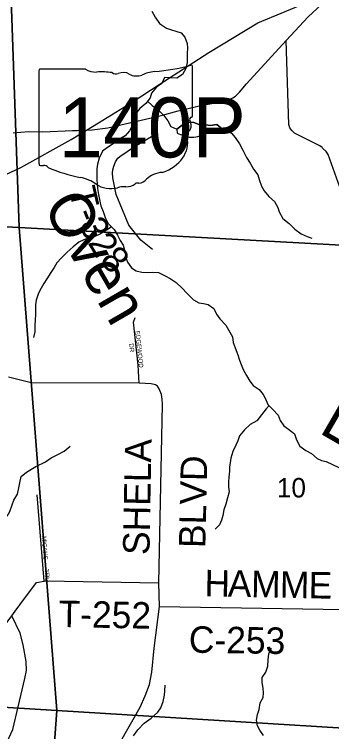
# Model space of a CAD drawing. Extents: x 1624196 to 2029251, y 146837 to 440034.
# Drawn here: x 1866396 to 1869991, y 270363 to 278490 of the extents above; entities that cross this region are included whole.
import ezdxf

# ---------------------------------------------------------------- set-up
doc = ezdxf.new("R2010")
doc.units = 0
for name, color, linetype in [('GM_P_State_Alignment', 7, 'Continuous'), ('GM_P_State_Location', 7, 'Continuous'), ('GM_P_State_Shield', 7, 'Continuous'), ('GM_X_County_Road', 7, 'Continuous'), ('GM_X_County_Road_Text', 7, 'Continuous'), ('GM_X_Minor_Lake', 7, 'Continuous'), ('GM_X_Minor_River', 7, 'Continuous'), ('GM_X_Minor_River_Text', 7, 'Continuous'), ('GM_X_Section', 7, 'Continuous'), ('GM_X_Section_Text', 7, 'Continuous'), ('GM_X_State_Route', 7, 'Continuous'), ('GM_X_Township_Road', 7, 'Continuous'), ('GM_X_Township_Road_Text', 7, 'Continuous'), ('GM_X_Township_Subdivision', 7, 'Continuous'), ('GM_X_Township_Subdivision_Text', 7, 'Continuous')]:
    doc.layers.add(name, color=color, linetype=linetype)

msp = doc.modelspace()

# ---------------------------------------------------------------- linework, layer by layer
at = {"layer": 'GM_P_State_Alignment'}
for points in [[(1867348.5, 277261), (1867740.4, 277501.5), (1868036.8, 277693.6), (1868599.3, 278058.2), (1869156.1, 278392.2), (1869792.3, 278662.6), (1870063.5, 278785.3), (1870460.4, 278964.8), (1871144.4, 279012.5), (1871212, 279012.5), (1872003.4, 279012.5), (1872655.6, 278996.6), (1872814.3, 279012), (1873399, 279068.6)], [(1867214.4, 277178.7), (1867348.5, 277261)], [(1861874.5, 274742.2), (1862064.2, 274850.8), (1862146.9, 274886.5), (1862221.6, 274909.2), (1862468.2, 274980.7), (1862817.1, 275066.7), (1863068.6, 275126.7), (1863088.2, 275172.1), (1863130.1, 275268.7), (1863334.2, 275354.2), (1863587.6, 275464), (1863663, 275496.7), (1863811.4, 275560.9), (1863954.5, 275640.5), (1864133.3, 275718.1), (1864797.6, 276006.3), (1865481.6, 276292.6), (1866467.8, 276753.9), (1867040.5, 277072), (1867214.4, 277178.7)]]:
    msp.add_lwpolyline(points, dxfattribs=at)
at = {"layer": 'GM_P_State_Shield'}
for p, q in [((1866675.2, 277851.2), (1866675.2, 276794.6)), ((1867202, 277869.4), (1866692.4, 277869.4)), ((1868415.4, 277342.9), (1868415.4, 277895.6)), ((1868415.3, 277343), (1868415.4, 277342.9))]:
    msp.add_line(p, q, dxfattribs=at)
for centre, major_axis, start_param, end_param in [((1866695.2, 277853.5), (20.2, 0), 1.712693, 3.28349), ((1867323.4, 277992.1), (195.5, 0), 4.042523, 4.731795), ((1867795.5, 279310), (1845.5, 0), 4.814394, 5.042369), ((1868396.1, 277897.9), (19.4, 0), 6.141152, 7.989035), ((1867388.2, 277276.2), (702, 0), 1.404758, 1.657858), ((1867547.6, 277859), (56.4, 0), 3.836095, 5.185415), ((1867630.4, 277736.8), (117.3, 0), 0.950623, 2.079405), ((1867781.8, 277904.3), (141.1, 0), 4.081561, 5.145723), ((1868030.9, 277546.7), (371.3, 0), 1.699011, 2.107814), ((1868411, 277302.3), (30, 0), 1.883978, 3.671073), ((1868220.2, 277232.4), (180, 0), 5.934695, 6.695948), ((1868394.8, 277340.7), (20.7, 0), 5.05454, 6.418171), ((1868484.8, 277111.5), (130.9, 0), 2.387724, 3.262537), ((1867898.9, 277041.2), (461.6, 0), 5.101752, 6.440018), ((1866695.4, 276792.3), (20.3, 0), 3.00124, 4.508301), ((1866698.4, 276900.4), (155.2, 0), 4.665946, 4.897461), ((1866730.2, 276733.6), (56, 0), 0.519207, 1.627899), ((1867436.8, 277683), (1332.7, 0), 4.195997, 4.488961), ((1867039.5, 276319.9), (417, 0), 0.823519, 1.323587), ((1868093.6, 276497.9), (252.8, 0), 1.647645, 2.488434), ((1867490.4, 276728.4), (264.6, 0), 4.026481, 4.996735), ((1867662.7, 276649.3), (141, 0), 4.691044, 5.507374), ((1867790.2, 276546.9), (39.7, 0), 1.147584, 2.315152), ((1867773.3, 276692.2), (149.1, 0), 4.937069, 5.64225), ((1867643.3, 276363.1), (217.4, 0), 1.495662, 1.94098)]:
    msp.add_ellipse(centre, major_axis=major_axis, ratio=0.8, start_param=start_param, end_param=end_param, dxfattribs=at)
at = {"layer": 'GM_X_County_Road'}
for points in [[(1868041.8, 271781.7), (1868033.7, 272048.3), (1868074.8, 274068), (1868071.3, 274130.9), (1868064.3, 274182.5), (1868037, 274247.1), (1868016.1, 274277.8), (1867995.5, 274293.7), (1867946.8, 274302.3), (1867809, 274312.2), (1866587.5, 274314.3), (1866329.7, 274381.2)], [(1866646.8, 267515.1), (1866874.7, 267543), (1867025.1, 267561.1), (1867079.3, 267579.1), (1867148.5, 267621.3), (1867205.7, 267684.5), (1867254.5, 267863.2), (1867359.7, 268076.7), (1867416.6, 268218.5), (1867445.5, 268362.4), (1867458.4, 268492.5), (1867424.5, 268793.1), (1867389.6, 269254), (1867374.8, 269424.3), (1867356.1, 269620.7), (1867409.5, 269828.6), (1867508.7, 270046.1), (1867585.8, 270227.8), (1867820.2, 270640.6), (1867879, 270770.3), (1867927.8, 270896.1), (1867954.6, 271036.1), (1867980.5, 271310.3), (1868041.8, 271781.7)], [(1868041.8, 271781.7), (1870358.7, 271742.5)]]:
    msp.add_lwpolyline(points, dxfattribs=at)
at = {"layer": 'GM_X_Minor_Lake'}
for points in [[(1868752.3, 277189.1), (1868688.5, 277241.6), (1868614.3, 277231.9), (1868564.3, 277238.1), (1868498.2, 277238.4), (1868428.2, 277264.8), (1868366.1, 277267.1), (1868297.8, 277235.4), (1868235.5, 277187.5)], [(1868235.5, 277187.5), (1868239.3, 277145.4), (1868279.3, 277129.2), (1868327.4, 277116.9), (1868375.3, 277098.7), (1868427.4, 277098.4), (1868475.5, 277106.2), (1868519.7, 277122), (1868565.8, 277143.9), (1868615.9, 277149.7), (1868662, 277151.5), (1868706.2, 277175.3), (1868752.3, 277189.1)]]:
    msp.add_lwpolyline(points, dxfattribs=at)
at = {"layer": 'GM_X_Minor_River'}
for points in [[(1867953, 278524.2), (1867990.8, 278457.9), (1868038.5, 278387.5), (1868118.4, 278335), (1868174.4, 278314.6), (1868224.4, 278298.4), (1868286.4, 278282), (1868326.3, 278231.7), (1868352, 278161.4), (1868355.8, 278107.3), (1868355.5, 278047.1), (1868355.3, 277997), (1868353, 277942.9), (1868338.7, 277874.8), (1868302.4, 277808.8), (1868236.1, 277765), (1868164, 277771.3), (1868097.9, 277775.6), (1868065.6, 277707.6), (1868007.3, 277663.8), (1867950.9, 277595.9), (1867934.7, 277545.8), (1867886.3, 277479.9), (1867815.9, 277424.1), (1867765.6, 277360.1), (1867749.2, 277294.1), (1867737, 277240), (1867700.6, 277170), (1867650.3, 277112.1), (1867578, 277070.3), (1867525.7, 277030.4), (1867449.4, 276980.7), (1867395.1, 276938.8), (1867356.7, 276860.8), (1867338.4, 276792.7), (1867330.2, 276740.6), (1867329.6, 276620.3), (1867333.4, 276566.2), (1867337.2, 276516), (1867348.9, 276447.8), (1867364.6, 276371.5), (1867376.4, 276319.3), (1867402.1, 276255.1), (1867425.9, 276186.8), (1867457.6, 276120.5), (1867525.4, 276052), (1867565.2, 275987.6), (1867595, 275929.3), (1867628.8, 275875), (1867646.5, 275802.8), (1867658.2, 275736.6), (1867678, 275682.3), (1867721.8, 275618), (1867777.7, 275585.6), (1867839.7, 275567.3), (1867907.9, 275567), (1867962, 275570.7), (1868030, 275566.4), (1868104, 275528), (1868159.9, 275497.6), (1868227.8, 275451.2), (1868295.6, 275386.7), (1868349.5, 275330.3), (1868425.3, 275255.8), (1868487.2, 275221.4), (1868539.2, 275213.2), (1868591.3, 275202.9), (1868655.2, 275158.5), (1868684.9, 275092.2), (1868722.8, 275039.9), (1868790.6, 274969.4), (1868836.3, 274891), (1868866.1, 274836.7), (1868875.8, 274770.5), (1868897.6, 274712.2), (1868929.3, 274631.9), (1868947, 274573.7), (1868966.8, 274523.4), (1868986.6, 274465.2), (1869024.4, 274398.9), (1869062.2, 274334.5), (1869102, 274284.2), (1869169.9, 274239.8)], [(1867905.4, 277505.9), (1867956.3, 277455.5), (1868024.2, 277407.1), (1868090, 277344.6), (1868135.8, 277282.2), (1868169.6, 277217.9), (1868235.5, 277187.5), (1868297.8, 277235.4), (1868366.1, 277267.1), (1868428.2, 277264.8), (1868498.2, 277238.4), (1868564.3, 277238.1), (1868614.3, 277231.9), (1868688.5, 277241.6), (1868752.3, 277189.1), (1868800.4, 277186.9), (1868856.3, 277144.5), (1868896.1, 277094.2), (1868945.9, 277023.8), (1868983.6, 276951.5), (1869027.3, 276867), (1869069.1, 276802.7), (1869106.9, 276736.3), (1869154.6, 276670), (1869170.4, 276619.8), (1869194.1, 276541.5), (1869225.9, 276489.2), (1869279.8, 276426.8), (1869341.6, 276370.3), (1869379.4, 276302), (1869395.2, 276251.8), (1869438.9, 276177.4), (1869510.7, 276118.9), (1869572.6, 276054.5), (1869646.4, 276004), (1869714.4, 275973.6), (1869766.4, 275955.3)], [(1867495.5, 276082.2), (1867457.3, 276054.3), (1867371, 276002.6), (1867300.7, 275970.8), (1867232.5, 275955.1), (1867182.4, 275935.3), (1867128.2, 275909.5), (1867061.8, 275855.6), (1866993.5, 275795.8), (1866929.1, 275732), (1866878.8, 275676), (1866846.5, 275622.1), (1866810.2, 275566.1), (1866763.8, 275492.1), (1866731.5, 275440.1), (1866701.2, 275386.1), (1866670.9, 275330.1), (1866642.5, 275252.1), (1866634.3, 275198), (1866636, 275141.8), (1866635.8, 275083.7), (1866631.5, 275031.6), (1866629.2, 274961.4), (1866628.9, 274893.2), (1866614.6, 274829.1)], [(1869169.9, 274239.8), (1869215.7, 274183.4), (1869239.5, 274133.2), (1869269.3, 274070.9), (1869327.1, 274008.5), (1869384.9, 273950.1), (1869406.7, 273887.8), (1869448.5, 273829.5), (1869500.4, 273791.1), (1869570.3, 273738.7), (1869594, 273670.4), (1869631.8, 273598), (1869699.6, 273547.6), (1869761.6, 273515.2), (1869825.4, 273458.8), (1869877.4, 273434.5), (1869927.4, 273424.2), (1870073.7, 273357.2)], [(1869281, 274058.2), (1869249, 274020.9), (1869194.7, 273951), (1869142.3, 273885), (1869068, 273843.3), (1869003.6, 273781.4), (1868947.2, 273713.5), (1868927, 273659.5), (1868904.7, 273607.4), (1868872.3, 273537.4), (1868850, 273461.3), (1868834.6, 273361.6)], [(1866638.3, 273369.1), (1866750.6, 273421), (1866812.9, 273466.8), (1866889.2, 273504.5), (1866959.4, 273540.3), (1867027.8, 273596.1)], [(1866316.1, 272805), (1866346.5, 272858.9), (1866371, 272932.8), (1866389.4, 272984.7), (1866429.9, 273054.4), (1866446.5, 273126.4), (1866458.9, 273182.3), (1866471.5, 273252.3), (1866531.8, 273303.9), (1866638.3, 273369.1)], [(1868834.6, 273361.6), (1868832.3, 273313.8), (1868825.8, 273245.8), (1868821.4, 273193.8), (1868820.9, 273131.7), (1868830.5, 273081.6), (1868811.9, 273011.7), (1868791.4, 272939.8), (1868770.9, 272875.8), (1868756.4, 272813.9), (1868744, 272757.9), (1868719.6, 272706), (1868669.2, 272658.4)], [(1869218.4, 270319.5), (1869176.9, 270379.9), (1869151.3, 270430.1), (1869139.8, 270494.3), (1869152.3, 270558.3), (1869168.8, 270614.2), (1869179.4, 270690.2), (1869213.8, 270752), (1869220.2, 270804), (1869214.6, 270854.1), (1869203.2, 270920.3), (1869201.6, 270976.3), (1869244.1, 271038.1), (1869266.6, 271106), (1869271.1, 271176), (1869277.7, 271244), (1869310.1, 271307.8)], [(1867747.4, 270317), (1867795.9, 270382.7), (1867868.5, 270460.2), (1867946.9, 270517.7), (1868021.3, 270583.2), (1868053.7, 270635), (1868082.3, 270704.8), (1868096.8, 270776.8), (1868101.2, 270826.8), (1868103.7, 270890.9)]]:
    msp.add_lwpolyline(points, dxfattribs=at)
at = {"layer": 'GM_X_Section'}
for points in [[(1862193.5, 281747.1), (1866257.2, 281575.1), (1866452.3, 276073.9), (1861882.7, 276297.8)], [(1866257.2, 281575.1), (1872946.7, 281242), (1872577.6, 275738.7), (1866452.3, 276073.9)], [(1866452.3, 276073.9), (1872577.6, 275738.7), (1872207.6, 270274.4), (1866878.3, 270602.6)], [(1872207.6, 270274.4), (1871875.5, 264953), (1866483.9, 265233.4), (1866878.3, 270602.6)]]:
    msp.add_lwpolyline(points, close=True, dxfattribs=at)
for points in [[(1861882.7, 276297.8), (1866452.3, 276073.9), (1866878.3, 270602.6), (1862104.9, 270898.9)], [(1862408.7, 270235.8), (1862371.1, 270371.9), (1862333.7, 270542.1), (1862296.3, 270712.2), (1862238.5, 270776.4), (1862162.8, 270850.7), (1862104.9, 270898.9), (1866878.3, 270602.6), (1866483.9, 265233.4)]]:
    msp.add_lwpolyline(points, dxfattribs=at)
at = {"layer": 'GM_X_State_Route'}
for points in [[(1868320.3, 277411.9), (1868503.4, 277455.8), (1868738.6, 277499.6), (1868813.9, 277515.9), (1868871.9, 277545.4), (1868901.4, 277564.8), (1868946.2, 277606.6), (1869027.7, 277701.2), (1869473.8, 278193.6), (1869725.8, 278460.9), (1869876.8, 278601.4), (1870063.5, 278785.3)], [(1868059.8, 277342.8), (1868253, 277395.8), (1868320.3, 277411.9)], [(1867214.4, 277178.7), (1867276.4, 277180.8), (1867454.9, 277205.6), (1868030.1, 277334.6), (1868059.8, 277342.8)], [(1866383.8, 277146.1), (1866554.9, 277161), (1866718.5, 277158.5), (1867053.2, 277173.4), (1867107.3, 277175.2)], [(1867107.3, 277175.2), (1867214.4, 277178.7)]]:
    msp.add_lwpolyline(points, dxfattribs=at)
at = {"layer": 'GM_X_Township_Road'}
for points in [[(1869881.3, 276979.5), (1869857, 276999.3), (1869570, 277143.5), (1869538.3, 277173.4), (1869515.8, 277206), (1869507.1, 277242.7), (1869473.8, 278193.6)], [(1867961.2, 275825.5), (1867830.7, 275932.8), (1867694.5, 276103.1), (1867550.6, 276448), (1867513, 276639), (1867507.8, 276692.9), (1867511.8, 276726.6), (1867524.8, 276769.3), (1867540.4, 276819.5), (1867567, 276859.3), (1867590.5, 276880.7), (1867758.4, 276990.9), (1867968.8, 277118.5), (1867981.2, 277147), (1867993.5, 277181.7), (1868008.2, 277218.3), (1868030.1, 277334.6)], [(1870818.5, 275147.3), (1870801.2, 275733.2), (1870787.2, 275772.3), (1870772.9, 275796.8), (1870754.6, 275811.1), (1870734.2, 275824.3), (1870510.1, 275869.4), (1870378.3, 275917.3), (1870342.3, 275939.7), (1870303.5, 275966.2), (1870273.1, 276004.9), (1869950, 276901.8), (1869930.1, 276936.7), (1869891.3, 276971.4), (1869887.5, 276974.4), (1869881.3, 276979.5)], [(1866439.7, 271773.1), (1866459.4, 271799.4), (1866646.1, 272051.6), (1866734.2, 272067.9), (1866748.4, 272070.6), (1868033.7, 272048.3)], [(1863906.6, 271243.2), (1864137.3, 271413.3), (1865018.3, 271359), (1865193.1, 271326.6), (1865325.7, 271310.4), (1865435.8, 271297.5), (1865655.8, 271352.5), (1866034.4, 271433.4), (1866147.7, 271469), (1866176.3, 271471), (1866235.2, 271510.3), (1866256.3, 271527.3), (1866366.7, 271675.2), (1866425.5, 271754), (1866439.7, 271773.1)]]:
    msp.add_lwpolyline(points, dxfattribs=at)
at = {"layer": 'GM_X_Township_Subdivision'}
for points in [[(1867809, 274312.2), (1867797.8, 274515), (1867744.1, 275003.1), (1867762.9, 275055.1)], [(1866734.2, 272067.9), (1866652.8, 273047.9)], [(1866266.1, 270141.7), (1866379.9, 270386.4), (1866515.6, 270964.1), (1866532.5, 271054.9), (1866530, 271157), (1866497.6, 271347.7), (1866460.5, 271480.8), (1866366.7, 271675.2)]]:
    msp.add_lwpolyline(points, dxfattribs=at)

# ---------------------------------------------------------------- texts
at = {"layer": 'GM_P_State_Location'}
msp.add_text('140P', height=1, rotation=0.00001, dxfattribs=at).set_placement((1867102.4, 277207.2))
for s in ['s', 'r']:
    msp.add_text(s, height=1, dxfattribs=at).set_placement((1867525.8, 277252.7))
at = {"layer": 'GM_P_State_Shield'}
msp.add_text('140P', height=680, dxfattribs=at).set_placement((1866895.3, 276869.1))
at = {"layer": 'GM_X_County_Road_Text'}
for s, rotation, p in [('SHELA', 88.93491, (1867925.9, 272362.6)), ('BLVD', 88.7379, (1868559.5, 272441.5)), ('H', 358.8798, (1868547.8, 271897.6)), ('A', 358.87863, (1868811.8, 271892.5)), ('M', 358.87904, (1869075.7, 271887.3)), ('M', 358.88026, (1869401.3, 271881)), ('E', 358.87926, (1869726.8, 271874.6)), ('C-253', 359.1736, (1868370.8, 271258.4))]:
    msp.add_text(s, height=300, rotation=rotation, dxfattribs=at).set_placement(p)
at = {"layer": 'GM_X_Minor_River_Text'}
for s, height, rotation, p in [('Oven', 500.01, 299.99953, (1866710.6, 276314.5)), ('Lick', 500, 329.99818, (1869833.3, 273755.6))]:
    msp.add_text(s, height=height, rotation=rotation, dxfattribs=at).set_placement(p)
at = {"layer": 'GM_X_Section_Text'}
msp.add_text('10', height=221, rotation=0.00001, dxfattribs=at).set_placement((1869370.6, 273016.4))
at = {"layer": 'GM_X_Township_Road_Text'}
for s, rotation, p in [('T', 282.84397, (1867012.8, 276503.3)), ('-', 291.9958, (1867078.3, 276234.7)), ('3', 293.23368, (1867127.1, 276113.9)), ('2', 301.54171, (1867221.8, 275902)), ('8', 311.82752, (1867353.5, 275697.5)), ('T-252', 358.87679, (1866894.2, 271549.4))]:
    msp.add_text(s, height=300, rotation=rotation, dxfattribs=at).set_placement(p)
at = {"layer": 'GM_X_Township_Subdivision_Text'}
for s, rotation, p in [('EDGEWOOD', 275.7102, (1867767.3, 274900.2)), ('DR', 276.00542, (1867695.9, 274759.3)), ('MICAHS', 274.23819, (1866706.9, 272576.7)), ('TRL', 274.4045, (1866737.7, 272202.7))]:
    msp.add_text(s, height=50, rotation=rotation, dxfattribs=at).set_placement(p)

doc.saveas('drawing.dxf')
